// Mitsubishi GX Works2 project: 19.顺序控制   PLC: FX3U/FX3UC

PROGRAM MAIN
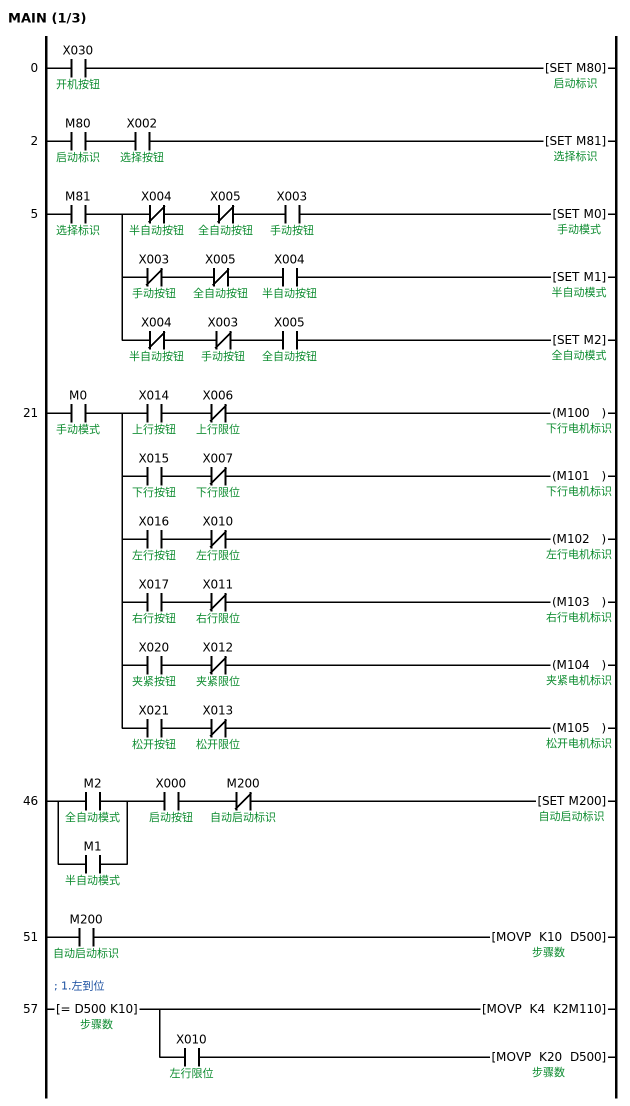
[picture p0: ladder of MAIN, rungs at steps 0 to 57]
0     LD      X030  ; 开机按钮
      SET     M80  ; 启动标识
2     LD      M80  ; 启动标识
      AND     X002  ; 选择按钮
      SET     M81  ; 选择标识
5     LD      M81  ; 选择标识
      MPS
      ANI     X004  ; 半自动按钮
      ANI     X005  ; 全自动按钮
      AND     X003  ; 手动按钮
      SET     M0  ; 手动模式
        [note] 模式选择
      MRD
      ANI     X003  ; 手动按钮
      ANI     X005  ; 全自动按钮
      AND     X004  ; 半自动按钮
      SET     M1  ; 半自动模式
      MPP
      ANI     X004  ; 半自动按钮
      ANI     X003  ; 手动按钮
      AND     X005  ; 全自动按钮
      SET     M2  ; 全自动模式
21    LD      M0  ; 手动模式
      MPS
      AND     X014  ; 上行按钮
      ANI     X006  ; 上行限位
      OUT     M100  ; 下行电机标识
        [note] 手动运行
      MRD
      AND     X015  ; 下行按钮
      ANI     X007  ; 下行限位
      OUT     M101  ; 下行电机标识
      MRD
      AND     X016  ; 左行按钮
      ANI     X010  ; 左行限位
      OUT     M102  ; 左行电机标识
      MRD
      AND     X017  ; 右行按钮
      ANI     X011  ; 右行限位
      OUT     M103  ; 右行电机标识
      MRD
      AND     X020  ; 夹紧按钮
      ANI     X012  ; 夹紧限位
      OUT     M104  ; 夹紧电机标识
      MPP
      AND     X021  ; 松开按钮
      ANI     X013  ; 松开限位
      OUT     M105  ; 松开电机标识
46    LD      M2  ; 全自动模式
      OR      M1  ; 半自动模式
      AND     X000  ; 启动按钮
      ANI     M200  ; 自动启动标识
      SET     M200  ; 自动启动标识
51    LD      M200  ; 自动启动标识
      MOVP    K10 D500  ; 步骤数
        [note] 把K10赋予D500
; 1.左到位
57    LD=     D500 K10  ; 步骤数
      MOVP    K4 K2M110
        [note] 左行（把100赋值给M110-M117）
      AND     X010  ; 左行限位
      MOVP    K20 D500
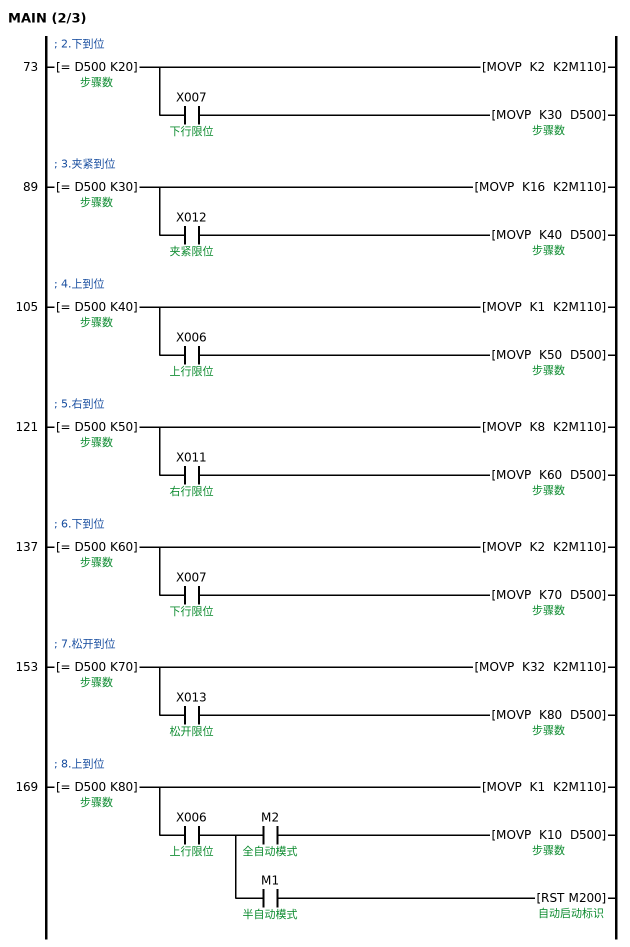
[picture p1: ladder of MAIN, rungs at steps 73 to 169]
; 2.下到位
73    LD=     D500 K20  ; 步骤数
      MOVP    K2 K2M110
        [note] 下行（把10赋值给M110-M117）
      AND     X007  ; 下行限位
      MOVP    K30 D500
; 3.夹紧到位
89    LD=     D500 K30  ; 步骤数
      MOVP    K16 K2M110
        [note] 夹紧（把10000赋值给M110-M117）
      AND     X012  ; 夹紧限位
      MOVP    K40 D500
; 4.上到位
105   LD=     D500 K40  ; 步骤数
      MOVP    K1 K2M110
        [note] 上行（把1赋值给M110-M117）
      AND     X006  ; 上行限位
      MOVP    K50 D500
; 5.右到位
121   LD=     D500 K50  ; 步骤数
      MOVP    K8 K2M110
        [note] 右行（把1000赋值给M110-M117）
      AND     X011  ; 右行限位
      MOVP    K60 D500
; 6.下到位
137   LD=     D500 K60  ; 步骤数
      MOVP    K2 K2M110
        [note] 下行（把10赋值给M110-M117）
      AND     X007  ; 下行限位
      MOVP    K70 D500
; 7.松开到位
153   LD=     D500 K70  ; 步骤数
      MOVP    K32 K2M110
        [note] 松开Y（把100000赋值给M110-M117）
      AND     X013  ; 松开限位
      MOVP    K80 D500
; 8.上到位
169   LD=     D500 K80  ; 步骤数
      MOVP    K1 K2M110
        [note] 上行(把1赋值给M110-M117)
      AND     X006  ; 上行限位
      MPS
      AND     M2  ; 全自动模式
      MOVP    K10 D500
        [note] 返回第一步
      MPP
      AND     M1  ; 半自动模式
      RST     M200  ; 自动启动标识
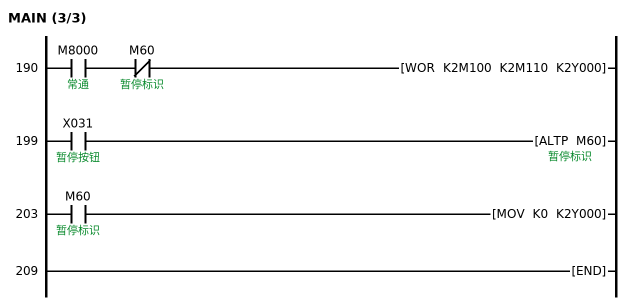
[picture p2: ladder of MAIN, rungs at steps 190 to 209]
190   LD      M8000  ; 常通
      ANI     M60  ; 暂停标识
      WOR     K2M100 K2M110 K2Y000  ; 上行电机
        [note] M100-M107或M110-M117谁通Y就通
199   LD      X031  ; 暂停按钮
      ALTP    M60
        [note] 单次操作，*1暂停，*2继续
203   LD      M60  ; 暂停标识
      MOV     K0 K2Y000
        [note] m60通把0赋值给所有Y
209   END
END_PROGRAM

// device comments not shown above
Y001  ; 下行电机
Y002  ; 左行电机
Y003  ; 右行电机
Y004  ; 夹紧电机
Y005  ; 松开电机
M106  ; 手动松开标识
M151  ; 自动上行标识
M152  ; 自动下行标识
M153  ; 自动左行标识
M154  ; 自动右行标识
M155  ; 自动夹紧标识
M156  ; 自动松开标识
M161  ; 上行转代标识
M162  ; 下行转代标识
M163  ; 左行转代标识
M164  ; 右行转代标识
M165  ; 夹紧转代标识
C0  ; 计次
